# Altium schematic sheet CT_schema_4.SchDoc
size 562 x 419 mm
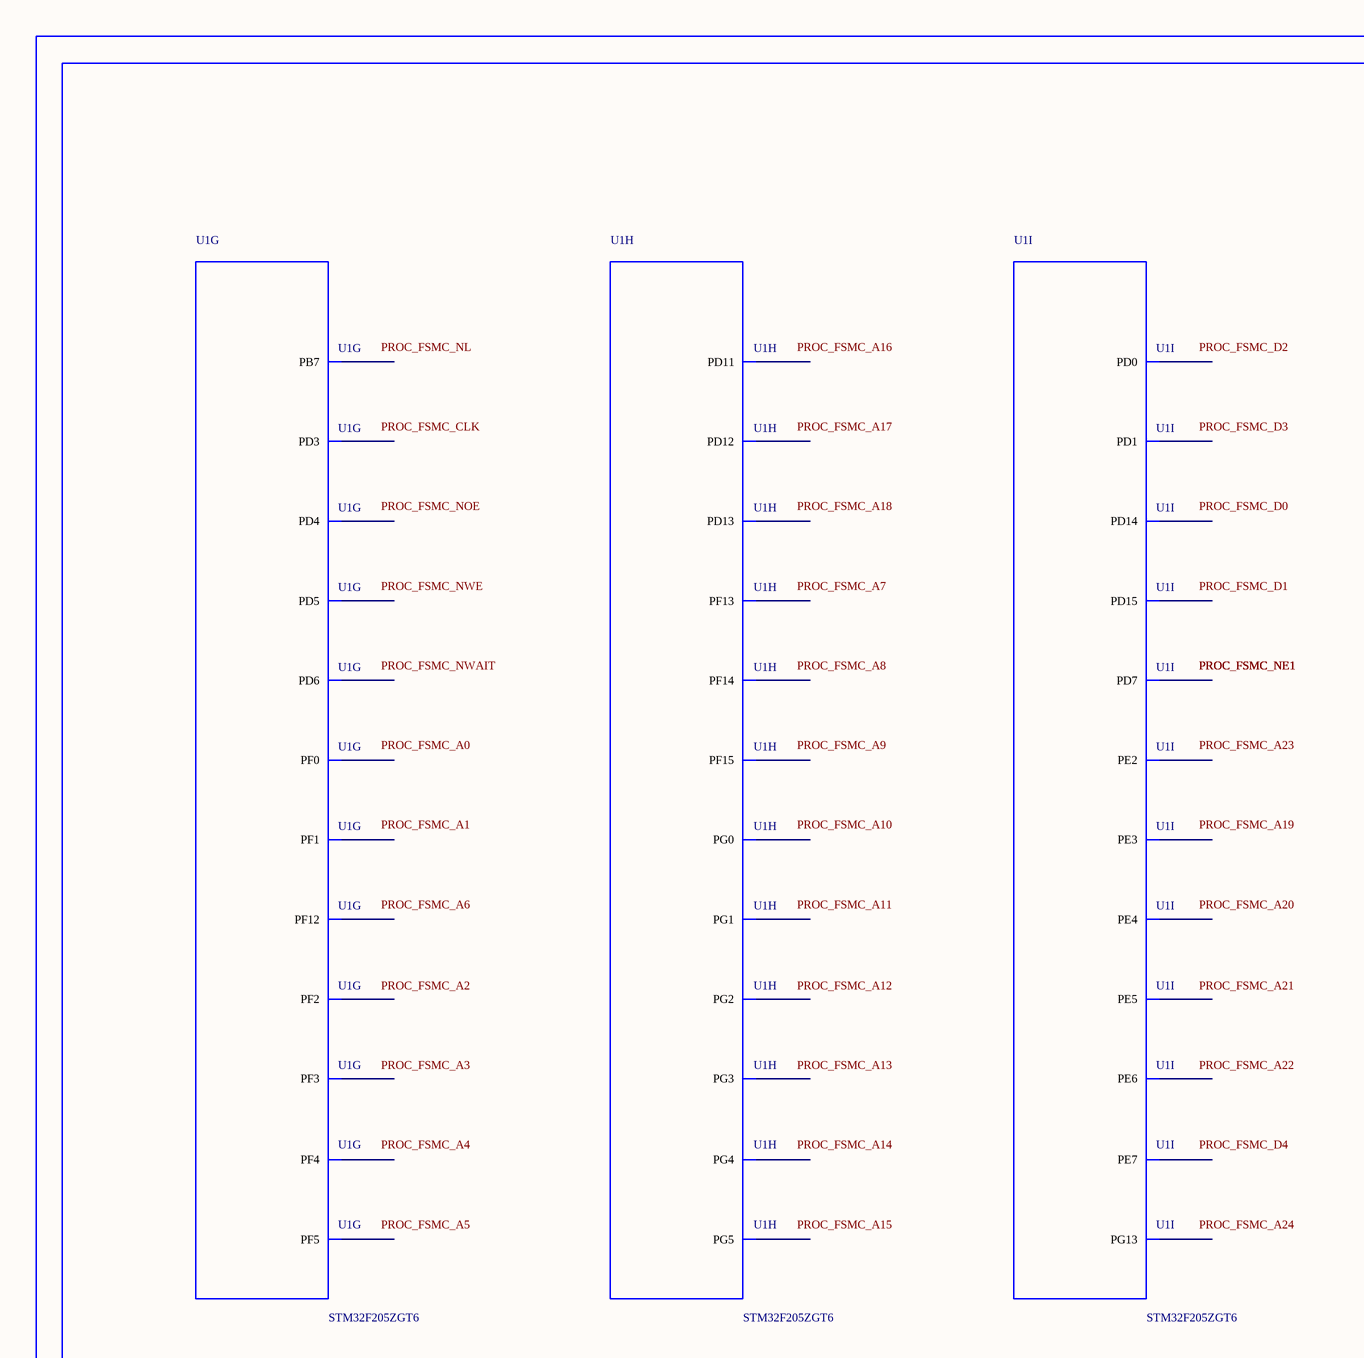
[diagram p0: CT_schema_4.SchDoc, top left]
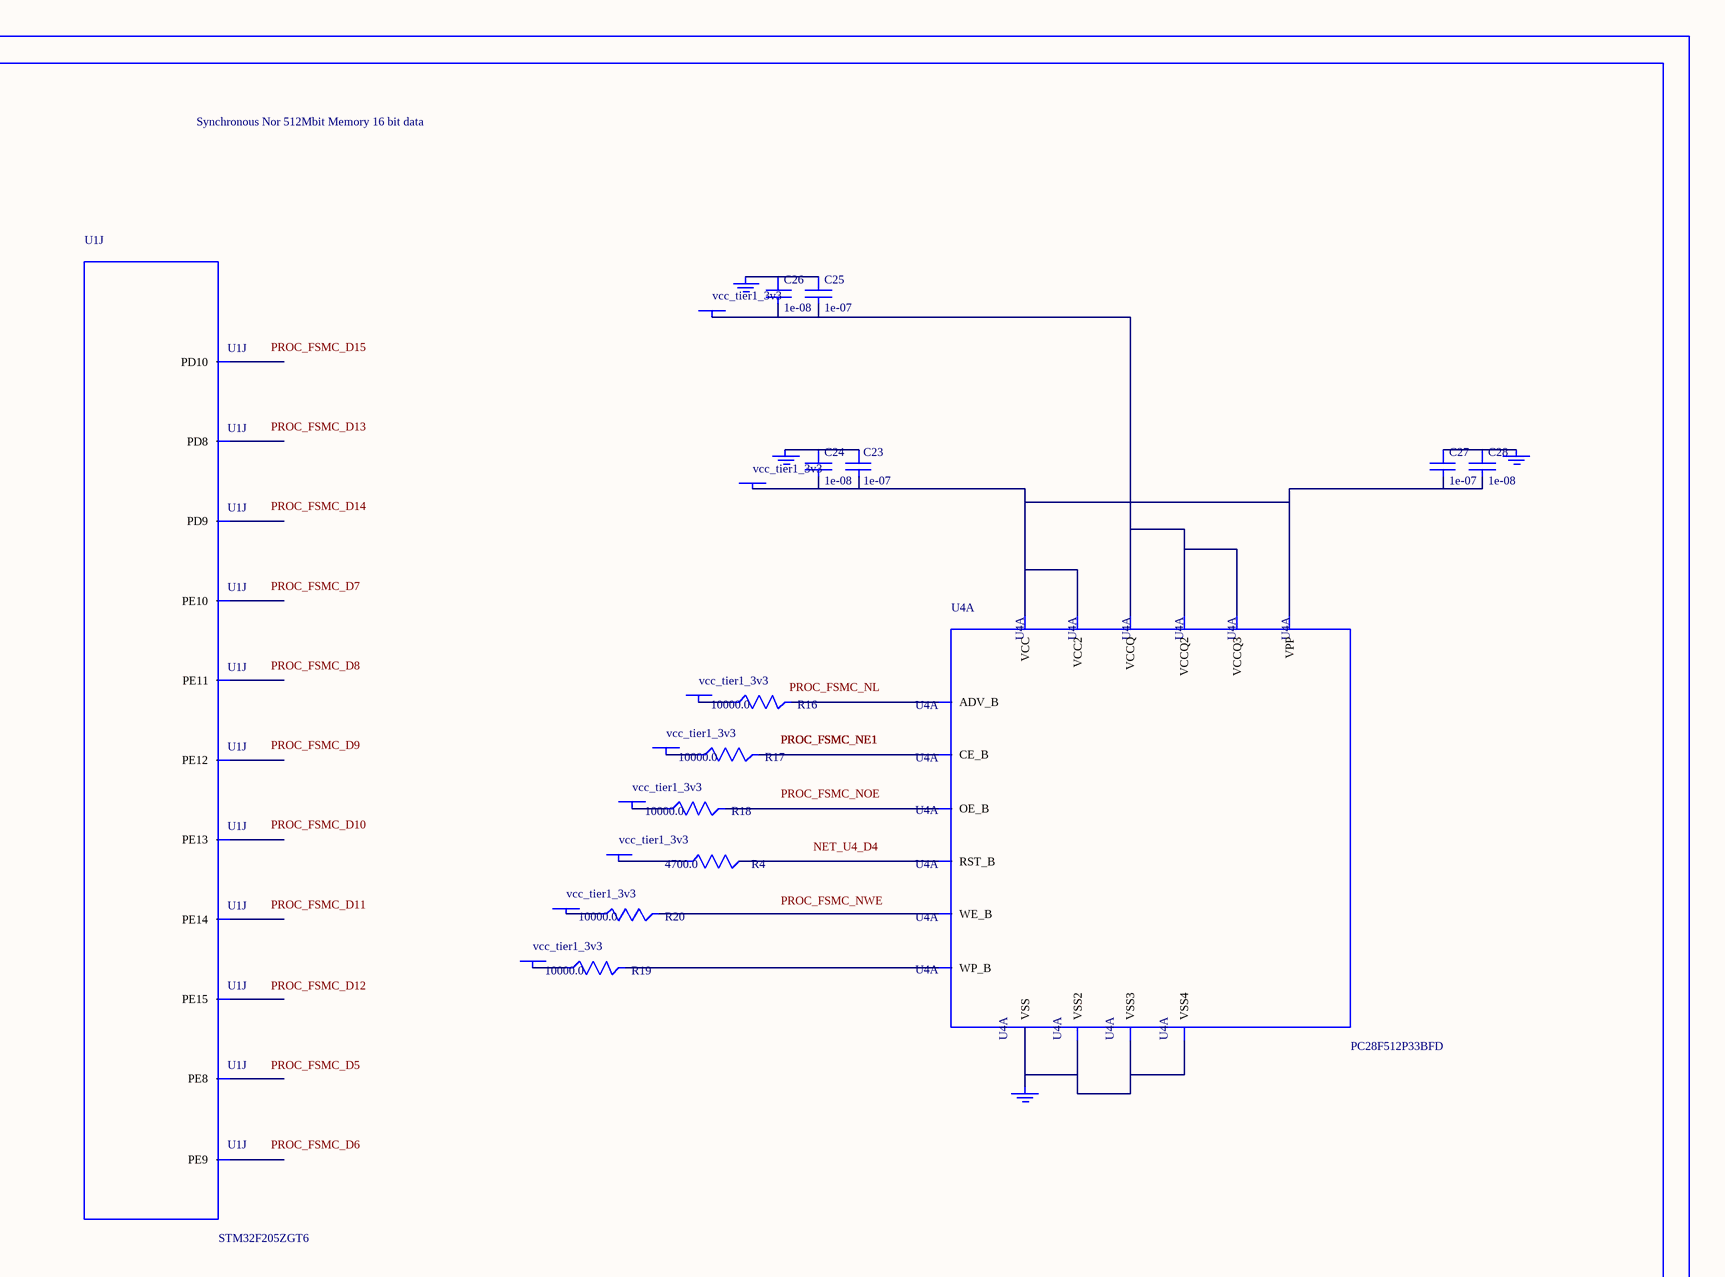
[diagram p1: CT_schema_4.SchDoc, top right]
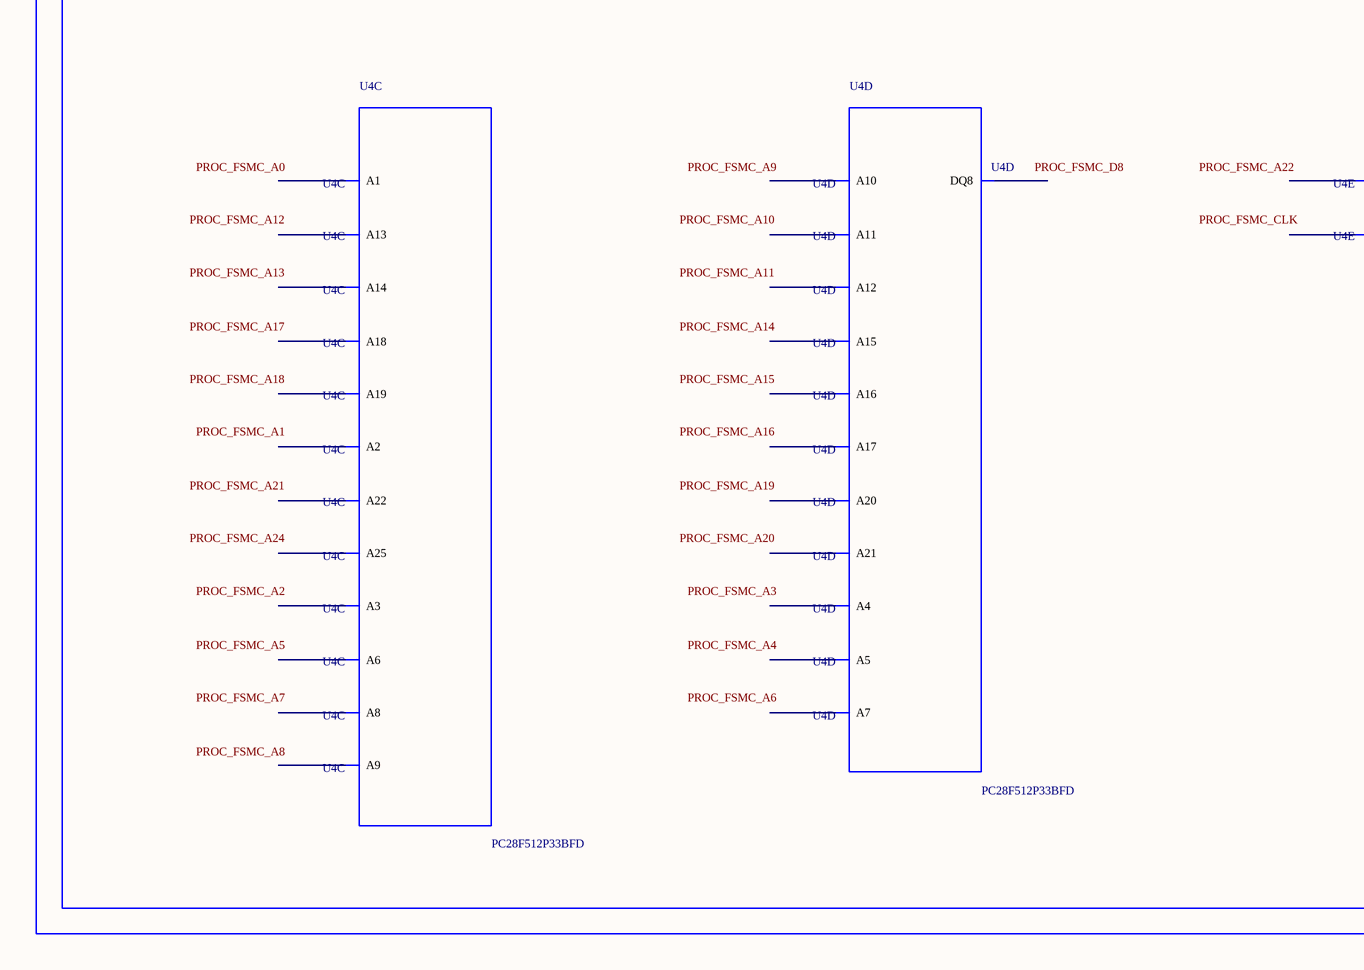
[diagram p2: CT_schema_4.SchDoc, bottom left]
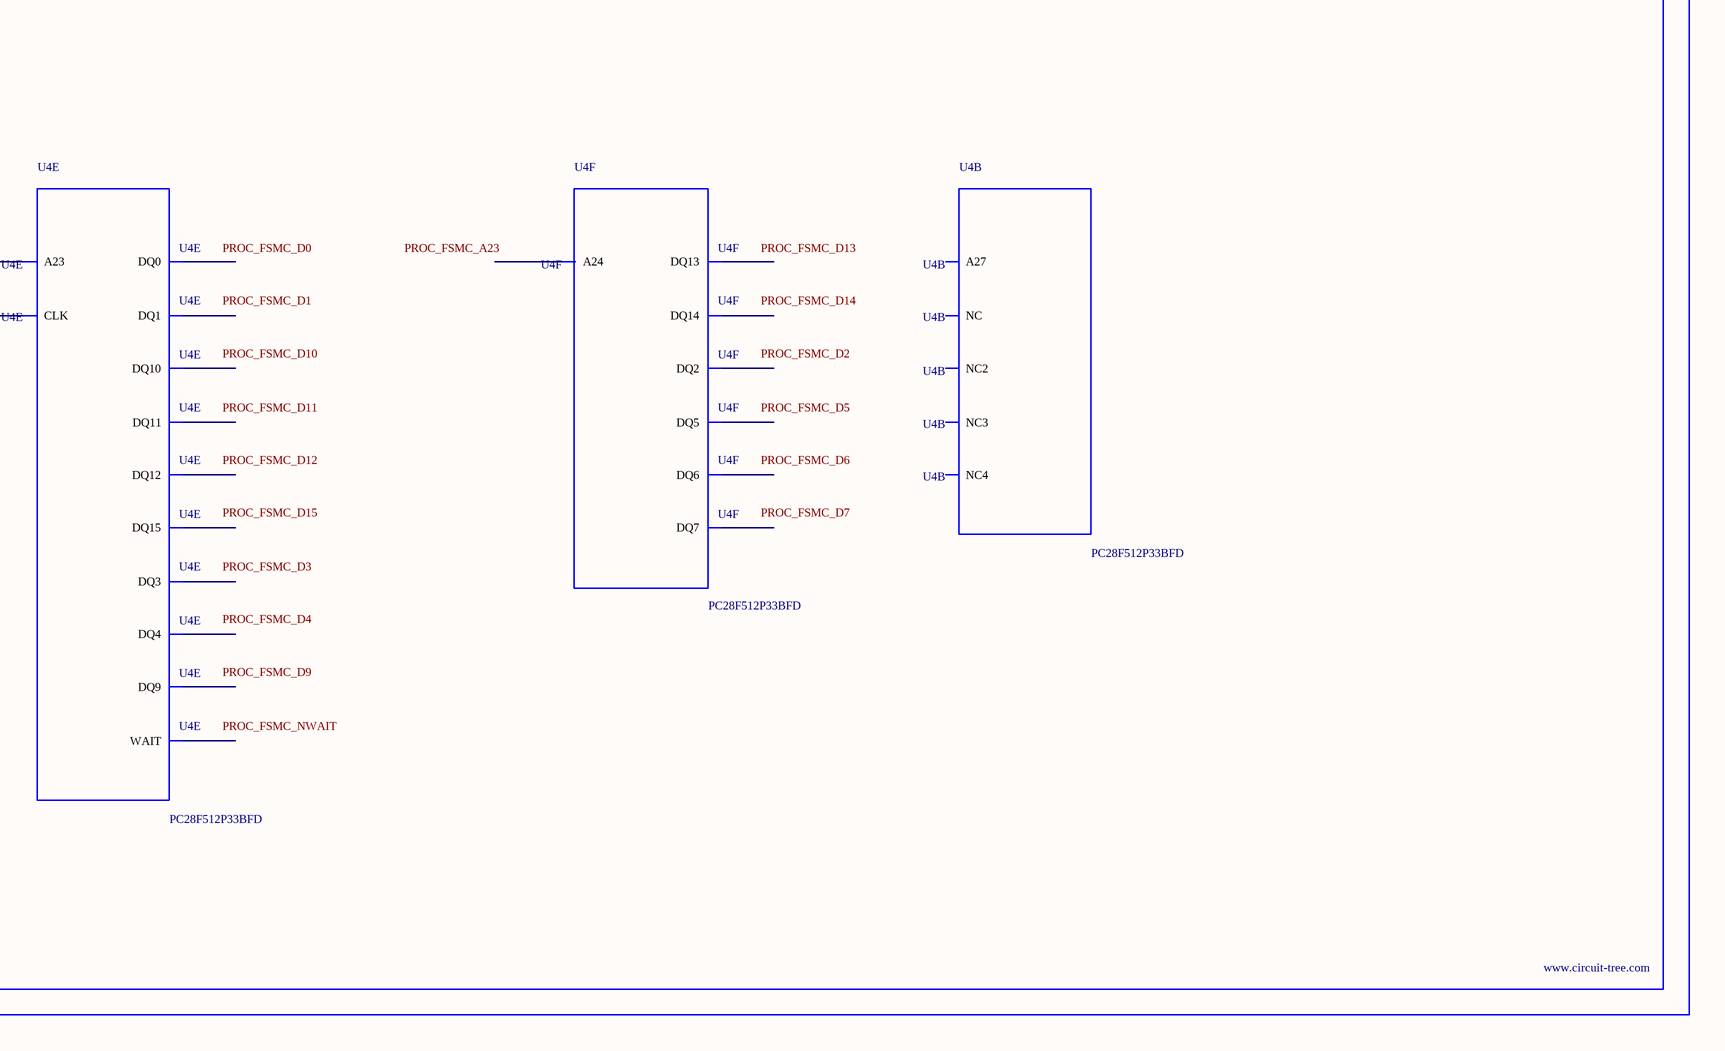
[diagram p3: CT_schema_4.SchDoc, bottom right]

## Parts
BORDER3  (no value)
C23  1e-07  [C0402]
C24  1e-08  [C0402]
C25  1e-07  [C0402]
C26  1e-08  [C0402]
C27  1e-07  [C0402]
C28  1e-08  [C0402]
GND_INSTANCE_3_0  (no value)
GND_INSTANCE_3_1  (no value)
GND_INSTANCE_3_2  (no value)
GND_INSTANCE_3_3  (no value)
POWER_INSTANCE_3_0  vcc_tier1_3v3
POWER_INSTANCE_3_1  vcc_tier1_3v3
POWER_INSTANCE_3_2  vcc_tier1_3v3
POWER_INSTANCE_3_3  vcc_tier1_3v3
POWER_INSTANCE_3_4  vcc_tier1_3v3
POWER_INSTANCE_3_5  vcc_tier1_3v3
POWER_INSTANCE_3_6  vcc_tier1_3v3
POWER_INSTANCE_3_7  vcc_tier1_3v3
R4  4700.0  [R0603]
R16  10000.0  [R0603]
R17  10000.0  [R0603]
R18  10000.0  [R0603]
R19  10000.0  [R0603]
R20  10000.0  [R0603]
U1  STM32F205ZGT6  [LQFP144]  (parts G,H,I,J of 12)
U4  PC28F512P33BFD  [PC28F512P33BFD]  (parts A,B,C,D,E,F of 6)

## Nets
NetC23_1: C23.1 C24.1 GND_INSTANCE_3_0.0(GND)
NetC23_2: C23.2 C24.2 C27.2 C28.2 POWER_INSTANCE_3_0.0(PWR) U4.A4(VPP) U4.A6(VCC) U4.H3(VCC2)
NetC25_1: C25.1 C26.1 GND_INSTANCE_3_1.0(GND)
NetC25_2: C25.2 C26.2 POWER_INSTANCE_3_1.0(PWR) U4.D5(VCCQ) U4.D6(VCCQ2) U4.G4(VCCQ3)
NetC27_1: C27.1 C28.1 GND_INSTANCE_3_2.0(GND)
NetGND_INSTANCE_3_3_0: GND_INSTANCE_3_3.0(GND) U4.B2(VSS) U4.H2(VSS2) U4.H4(VSS3) U4.H6(VSS4)
NetPOWER_INSTANCE_3_2_0: POWER_INSTANCE_3_2.0(PWR) R16.1
NetPOWER_INSTANCE_3_3_0: POWER_INSTANCE_3_3.0(PWR) R17.1
NetPOWER_INSTANCE_3_4_0: POWER_INSTANCE_3_4.0(PWR) R18.1
NetPOWER_INSTANCE_3_5_0: POWER_INSTANCE_3_5.0(PWR) R19.1
NetPOWER_INSTANCE_3_6_0: POWER_INSTANCE_3_6.0(PWR) R20.1
NetPOWER_INSTANCE_3_7_0: POWER_INSTANCE_3_7.0(PWR) R4.1
NetR4_2: R4.2 U4.D4(RST_B)
NetR16_2: R16.2 U4.F6(ADV_B)
NetR17_2: R17.2 U4.B4(CE_B)
NetR18_2: R18.2 U4.F8(OE_B)
NetR19_2: R19.2 U4.C6(WP_B)
NetR20_2: R20.2 U4.G8(WE_B)

Not connected (* = marked no-connect by the designer): U1 1(PE2) 2(PE3) 3(PE4) 4(PE5) 5(PE6) 10(PF0) 11(PF1) 12(PF2) 13(PF3) 14(PF4) 15(PF5) 50(PF12) 53(PF13) 54(PF14) 55(PF15) 56(PG0) 57(PG1) 58(PE7) 59(PE8) 60(PE9) 63(PE10) 64(PE11) 65(PE12) 66(PE13) 67(PE14) 68(PE15) 77(PD8) 78(PD9) 79(PD10) 80(PD11) 81(PD12) 82(PD13) 85(PD14) 86(PD15) 87(PG2) 88(PG3) 89(PG4) 90(PG5) 114(PD0) 115(PD1) 117(PD3) 118(PD4) 119(PD5) 122(PD6) 123(PD7) 128(PG13) 137(PB7); U4 A1 A2(A6) A3(A8) A5(A13) A7(A18) A8(A22) B1(A2) B3(A9) B5(A14) B6(A25) B7(A19) B8(NC) C1(A3) C2(A7) C3(A10) C4(A12) C5(A15) C7(A20) C8(A21) D1(A4) D2(A5) D3(A11) D7(A16) D8(A17) E1(DQ8) E2(DQ1) E3(DQ9) E4(DQ3) E5(DQ4) E6(CLK) E7(DQ15) E8(NC2) F1(NC3) F2(DQ0) F3(DQ10) F4(DQ11) F5(DQ12) F7(WAIT) G1(A23) G2(NC4) G3(DQ2) G5(DQ5) G6(DQ6) G7(DQ14) H1(A27) H5(DQ13) H7(DQ7) H8(A24)

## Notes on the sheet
- Labels drawn without touching a wire or pin: NET_U4_D4, PROC_FSMC_A0, PROC_FSMC_A1, PROC_FSMC_A2, PROC_FSMC_A3, PROC_FSMC_A4, PROC_FSMC_A5, PROC_FSMC_A6, PROC_FSMC_A7, PROC_FSMC_A8, PROC_FSMC_A9, PROC_FSMC_A10, PROC_FSMC_A11, PROC_FSMC_A12, PROC_FSMC_A13, PROC_FSMC_A14, PROC_FSMC_A15, PROC_FSMC_A16, PROC_FSMC_A17, PROC_FSMC_A18, PROC_FSMC_A19, PROC_FSMC_A20, PROC_FSMC_A21, PROC_FSMC_A22, PROC_FSMC_A23, PROC_FSMC_A24, PROC_FSMC_CLK, PROC_FSMC_D0, PROC_FSMC_D1, PROC_FSMC_D2, PROC_FSMC_D3, PROC_FSMC_D4, PROC_FSMC_D5, PROC_FSMC_D6, PROC_FSMC_D7, PROC_FSMC_D8, PROC_FSMC_D9, PROC_FSMC_D10, PROC_FSMC_D11, PROC_FSMC_D12, PROC_FSMC_D13, PROC_FSMC_D14, PROC_FSMC_D15, PROC_FSMC_NL, PROC_FSMC_NOE, PROC_FSMC_NWAIT, PROC_FSMC_NWE

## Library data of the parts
BORDER3 = BORDER_PAGE3
C23 C25 C27 = C0402C104K3RACTU
C24 C26 C28 = C0402C103K3RAC
GND_INSTANCE_3_0-GND_INSTANCE_3_3 = GND
POWER_INSTANCE_3_0-POWER_INSTANCE_3_7 = PWR
R4 = RC0603JR-074K7L
R16-R20 = RC0603JR-0710KL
